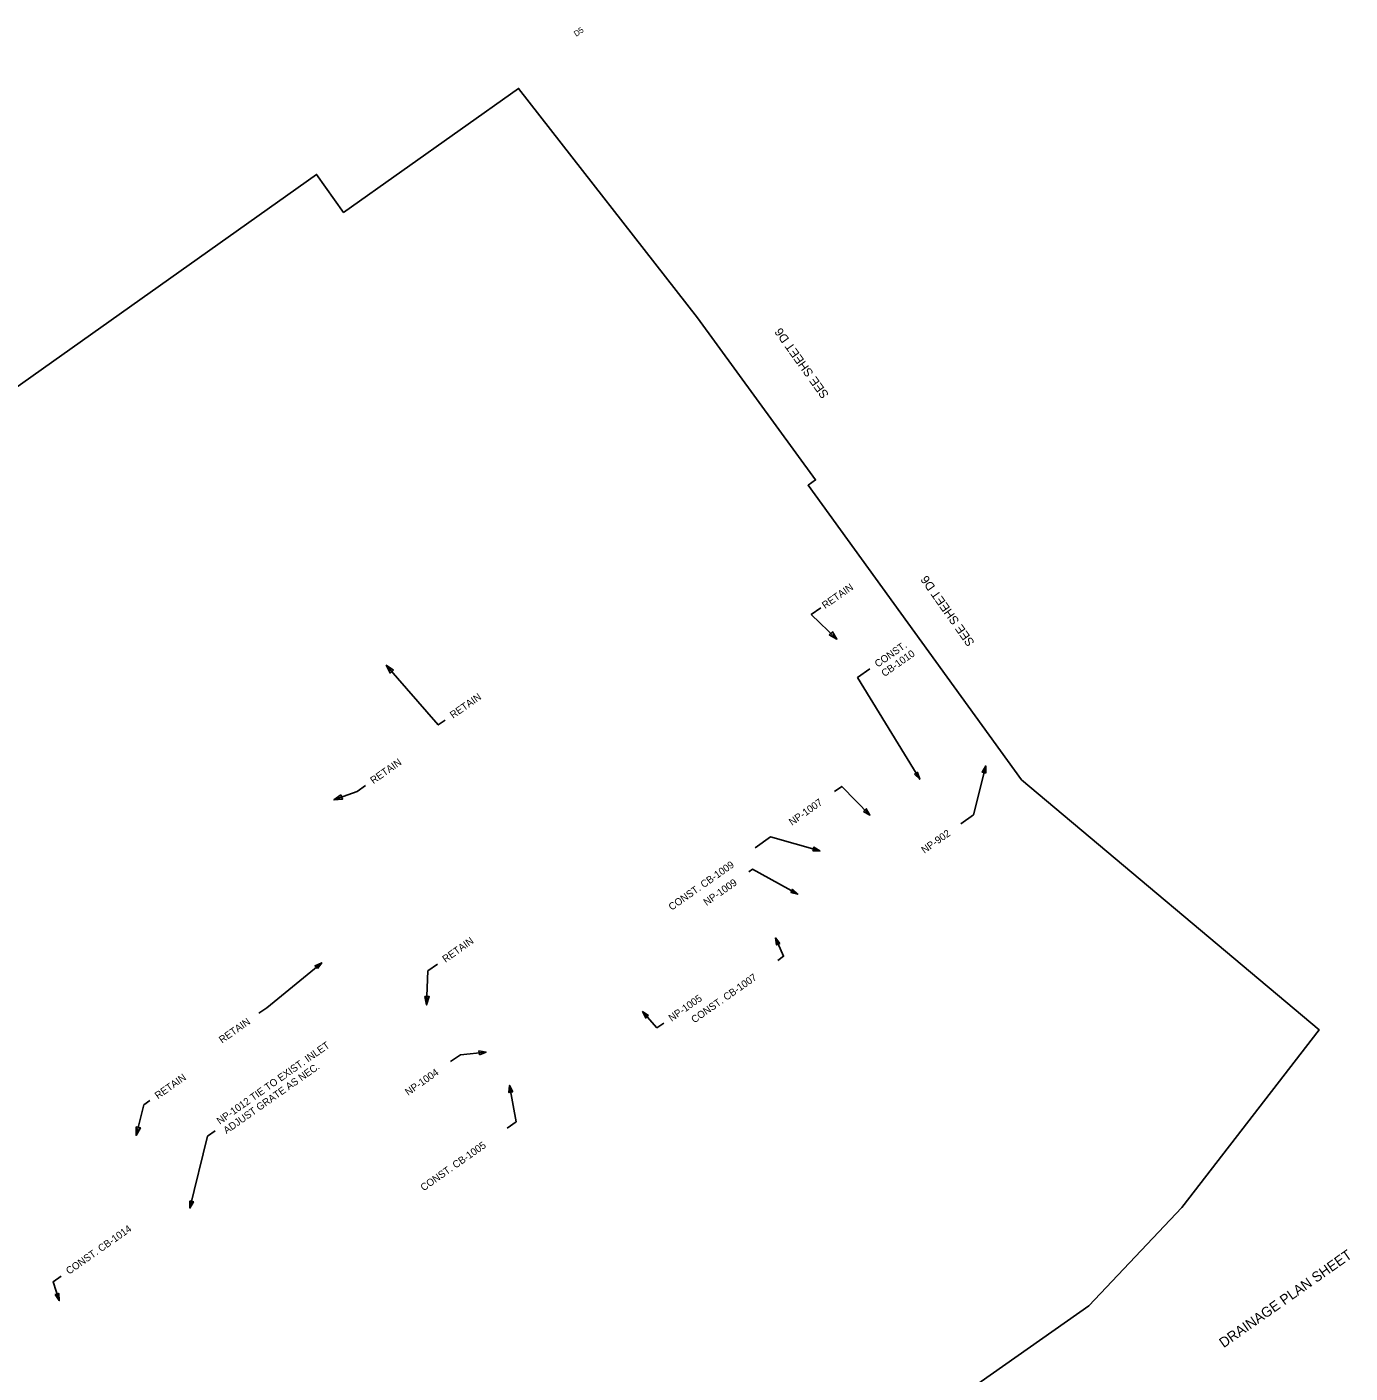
# Model space of a CAD drawing. Extents: x 1607509 to 1609318, y 1091210 to 1092975.
# Drawn here: x 1608401 to 1609318, y 1092042 to 1092975 of the extents above; entities that cross this region are included whole.
import ezdxf

# ---------------------------------------------------------------- set-up
doc = ezdxf.new("R2010")
doc.units = 0
for name, color, linetype in [('Plan_Clip', 7, 'Continuous'), ('RD_SHT_Bndy', 7, 'Continuous'), ('RD_SHT_MatchLine', 7, 'Continuous'), ('RD_TX_Drainage', 7, 'Continuous'), ('RD_TX_RoadID', 7, 'Continuous')]:
    doc.layers.add(name, color=color, linetype=linetype)

msp = doc.modelspace()

# ---------------------------------------------------------------- linework, layer by layer
at = {"layer": 'Plan_Clip'}
msp.add_lwpolyline([(1607607.31, 1091948.47), (1607743.52, 1091761.59), (1607741.15, 1091760.3), (1607913.93, 1091513.97), (1607933.88, 1091485.53), (1607952.11, 1091467.7), (1608052.12, 1091326.68), (1609136.73, 1092088.95), (1609201.03, 1092156.99), (1609296.24, 1092280.07), (1609089.98, 1092453.43), (1608942.19, 1092657.38), (1608947.36, 1092661.14), (1608865.54, 1092773.4), (1608741.72, 1092932.33), (1608620.57, 1092846.38), (1608601.84, 1092872.78), (1607509.19, 1092097.55)], close=True, dxfattribs=at)
msp.add_lwpolyline([(1607607.31, 1091948.47), (1607743.52, 1091761.59), (1607741.15, 1091760.3), (1607913.93, 1091513.97), (1607933.88, 1091485.53), (1607952.11, 1091467.7), (1608052.12, 1091326.68), (1609136.73, 1092088.95), (1609201.03, 1092156.99), (1609296.24, 1092280.07), (1609089.98, 1092453.43), (1608942.19, 1092657.38), (1608947.36, 1092661.14), (1608865.54, 1092773.4), (1608741.72, 1092932.33), (1608620.57, 1092846.38), (1608601.84, 1092872.78), (1607509.19, 1092097.55)], close=True, dxfattribs=at)
msp.add_lwpolyline([(1607607.31, 1091948.47), (1607743.52, 1091761.59), (1607741.15, 1091760.3), (1607913.93, 1091513.97), (1607933.88, 1091485.53), (1607952.11, 1091467.7), (1608052.12, 1091326.68), (1609136.73, 1092088.95), (1609201.03, 1092156.99), (1609296.24, 1092280.07), (1609089.98, 1092453.43), (1608942.19, 1092657.38), (1608947.36, 1092661.14), (1608865.54, 1092773.4), (1608741.72, 1092932.33), (1608620.57, 1092846.38), (1608601.84, 1092872.78), (1607509.19, 1092097.55)], close=True, dxfattribs=at)
msp.add_lwpolyline([(1607607.31, 1091948.47), (1607743.52, 1091761.59), (1607741.15, 1091760.3), (1607913.93, 1091513.97), (1607933.88, 1091485.53), (1607952.11, 1091467.7), (1608052.12, 1091326.68), (1609136.73, 1092088.95), (1609201.03, 1092156.99), (1609296.24, 1092280.07), (1609089.98, 1092453.43), (1608942.19, 1092657.38), (1608947.36, 1092661.14), (1608865.54, 1092773.4), (1608741.72, 1092932.33), (1608620.57, 1092846.38), (1608601.84, 1092872.78), (1607509.19, 1092097.55)], close=True, dxfattribs=at)
msp.add_lwpolyline([(1607607.31, 1091948.47), (1607743.52, 1091761.59), (1607741.15, 1091760.3), (1607913.93, 1091513.97), (1607933.88, 1091485.53), (1607952.11, 1091467.7), (1608052.12, 1091326.68), (1609136.73, 1092088.95), (1609201.03, 1092156.99), (1609296.24, 1092280.07), (1609089.98, 1092453.43), (1608942.19, 1092657.38), (1608947.36, 1092661.14), (1608865.54, 1092773.4), (1608741.72, 1092932.33), (1608620.57, 1092846.38), (1608601.84, 1092872.78), (1607509.19, 1092097.55)], close=True, dxfattribs=at)
at = {"layer": 'RD_TX_Drainage'}
for points in [[(1608950.94, 1092572.45), (1608944.37, 1092567.82), (1608962.2, 1092550.83)], [(1608690.87, 1092494.72), (1608686.11, 1092491.37), (1608650.14, 1092532.72)], [(1608984.99, 1092530.14), (1608976.51, 1092524.17), (1609019.52, 1092453.71)], [(1609048.1, 1092422.95), (1609056.81, 1092429.09), (1609065.25, 1092462.95)], [(1608635.68, 1092449.41), (1608629.85, 1092445.3), (1608613.86, 1092439.4)], [(1608960.48, 1092445.14), (1608965.59, 1092448.74), (1608984.99, 1092428.88)], [(1608905.53, 1092406.31), (1608916.09, 1092413.76), (1608950.45, 1092404.05)], [(1608901.3, 1092389.6), (1608903.78, 1092391.35), (1608935.11, 1092374)], [(1608921.23, 1092328.27), (1608925.28, 1092331.12), (1608919.63, 1092343.85)], [(1608561.9, 1092291.59), (1608567.3, 1092295.39), (1608605.4, 1092326.57)], [(1608685.58, 1092325.67), (1608678.89, 1092320.95), (1608678.08, 1092297.38)], [(1608842.23, 1092284.81), (1608837.59, 1092281.54), (1608827.58, 1092292.75)], [(1608694.67, 1092258.09), (1608701.44, 1092262.86), (1608719.24, 1092264.68)], [(1608733.74, 1092211.96), (1608740.05, 1092216.41), (1608735.53, 1092241.66)], [(1608486.47, 1092231.07), (1608482.25, 1092228.09), (1608476.87, 1092207.01)], [(1608531.65, 1092210.24), (1608526.2, 1092206.4), (1608514.19, 1092156.59)], [(1608424.94, 1092109.55), (1608419.35, 1092105.61), (1608423.6, 1092092.53)]]:
    msp.add_lwpolyline(points, dxfattribs=at)
for points in [[(1608956.93, 1092553.71), (1608962.2, 1092550.83), (1608959.08, 1092555.96)], [(1608655.12, 1092529.37), (1608650.14, 1092532.72), (1608652.77, 1092527.33)], [(1609015.9, 1092457.15), (1609019.52, 1092453.71), (1609018.11, 1092458.5)], [(1609065.34, 1092457.95), (1609065.25, 1092462.95), (1609062.83, 1092458.57)], [(1608618.76, 1092442.86), (1608613.86, 1092439.4), (1608619.83, 1092439.95)], [(1608980.69, 1092431.43), (1608984.99, 1092428.88), (1608982.54, 1092433.24)], [(1608945.45, 1092404.12), (1608950.45, 1092404.05), (1608946.16, 1092406.61)], [(1608930.26, 1092375.2), (1608935.11, 1092374), (1608931.51, 1092377.47)], [(1608922.77, 1092339.95), (1608919.63, 1092343.85), (1608920.41, 1092338.91)], [(1608602.48, 1092322.51), (1608605.4, 1092326.57), (1608600.85, 1092324.51)], [(1608676.73, 1092303.22), (1608678.08, 1092297.38), (1608679.83, 1092303.12)], [(1608831.77, 1092290.01), (1608827.58, 1092292.75), (1608829.84, 1092288.28)], [(1608714.56, 1092262.9), (1608719.24, 1092264.68), (1608714.3, 1092265.48)], [(1608737.65, 1092237.13), (1608735.53, 1092241.66), (1608735.1, 1092236.68)], [(1608476.8, 1092213.01), (1608476.87, 1092207.01), (1608479.81, 1092212.24)], [(1608514.06, 1092161.59), (1608514.19, 1092156.59), (1608516.58, 1092160.98)], [(1608420.88, 1092096.72), (1608423.6, 1092092.53), (1608423.34, 1092097.53)]]:
    msp.add_lwpolyline(points, close=True, dxfattribs=at)

# ---------------------------------------------------------------- texts
at = {"layer": 'RD_SHT_Bndy'}
msp.add_text('D5', height=4, rotation=35.16619, dxfattribs=at).set_placement((1608781.71, 1092967.97))
at = {"layer": 'RD_SHT_MatchLine'}
for rotation, p in [(125.50722, (1608956.88, 1092720.24)), (125.21745, (1609057.79, 1092548.46))]:
    msp.add_text('SEE SHEET D6', height=6, rotation=rotation, dxfattribs=at).set_placement(p)
at = {"layer": 'RD_TX_Drainage'}
for s, p in [('RETAIN', (1608954.01, 1092571.56)), ('CONST.', (1608990.52, 1092530.98)), ('CB-1010', (1608995.12, 1092524.44)), ('RETAIN', (1608696.4, 1092495.56)), ('RETAIN', (1608641.21, 1092450.25)), ('NP-1007', (1608931.12, 1092421.4)), ('NP-902', (1609022.79, 1092402.06)), ('CONST. CB-1009', (1608847.78, 1092362.57)), ('NP-1009', (1608871.94, 1092365.86)), ('RETAIN', (1608691.11, 1092326.5)), ('CONST. CB-1007', (1608863.48, 1092284.52)), ('NP-1005', (1608847.76, 1092285.64)), ('RETAIN', (1608536.4, 1092270.56)), ('NP-1012 TIE TO EXIST. INLET', (1608534.87, 1092214.35)), ('ADJUST GRATE AS NEC.', (1608539.48, 1092207.81)), ('NP-1004', (1608665.31, 1092234.34)), ('RETAIN', (1608492, 1092231.9)), ('CONST. CB-1005', (1608675.99, 1092168.22)), ('CONST. CB-1014', (1608430.47, 1092110.39))]:
    msp.add_text(s, height=5, rotation=35.16619, dxfattribs=at).set_placement(p)
at = {"layer": 'RD_TX_RoadID'}
msp.add_text('DRAINAGE PLAN SHEET', height=6.9833, rotation=35.16619, dxfattribs=at).set_placement((1609230.02, 1092059.55))

doc.saveas('drawing.dxf')
